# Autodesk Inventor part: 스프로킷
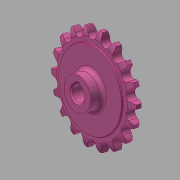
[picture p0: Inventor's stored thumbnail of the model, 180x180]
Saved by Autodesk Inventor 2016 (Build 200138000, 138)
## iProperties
Created: 2016-03
Part Number: 스프로킷
Material: 강철, 탄소
Document SubType Name: Modeling
Designer: mduedu
Density: 7.87 g/cm^3
Mass: 301.818 g
Surface Area: 124.882 cm^2
Volume: 38.3505 cm^3
Appearance: 분홍색
Author: mduedu
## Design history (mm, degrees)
sketch "스케치1"
  geometry: L1 (0, 5)-(29.5, 5); L2 (29.5, 5)-(29.5, 4.1); L3 (30, 3.6)-(33.625, 3.6); L4 (40, 2)-(40, 0); L5 (40, 0)-(0, 0); L6 (0, 0)-(0, 5); L7 (0, -5)-(29.5, -5); L8 (29.5, -5)-(29.5, -4.1); L9 (30, -3.6)-(33.625, -3.6); L10 (40, -2)-(40, 0); L11 (0, 0)-(0, -5); A1 r 13.5 centre (33.625, -9.9) between (40, 2) and (33.625, 3.6); A2 r 13.5 centre (33.625, 9.9) between (33.625, -3.6) and (40, -2); A3 r 0.5 centre (30, 4.1) between (29.5, 4.1) and (30, 3.6); A4 r 0.5 centre (30, -4.1) between (30, -3.6) and (29.5, -4.1); 2 further points
  constraints: 22 end point, 8 point on circle, 6 symmetric about line, 5 tangent, 4 centre point, 4 parallel, 4 point on line, 1 equal radius, 1 horizontal, 1 perpendicular, 1 other
  dimensions: "d0" = 80 diameter of L4 L6; "d2" = 59 diameter of L2 L6; "d3" = 1.6 vertical distance of L4.start L3.end; "d4" = 3.6 distance from line of L4.end L3; "d5" = 5 distance between parallel lines of L5 L1; "d6" = 13.5 radius of A1; "d15" = 0.5 radius of A3
revolve "회전1" sketch "스케치1" stored, may be unused: angle "d7" = 90 deg
sketch "스케치2" dims "d8" = 65.2, "d11" = 80
  geometry: L1 (0, 0)-(0, 32.6); A1 r 36.57 centre (0, 0) between (-16.231, 32.771) and (0, 36.57); A2 r 3.97 centre (0, 36.57) between (-3.866, 35.665) and (0, 32.6); A3 r 12.7 centre (-16.231, 32.771) between (-3.866, 35.665) and (-5.534, 39.615); A4 r 12.7 centre (16.231, 32.771) between (5.534, 39.615) and (3.866, 35.665); A5 r 3.97 centre (0, 36.57) between (0, 32.6) and (3.866, 35.665); A6 r 40 centre (0, 0) between (5.534, 39.615) and (-5.534, 39.615); 2 further points
  constraints: 12 point on circle, 6 centre point, 4 coincident, 3 symmetric about line, 2 end point, 1 point on line, 1 tangent, 1 vertical, 1 vertical alignment, 7 other
  dimensions: "d10" = 73.14 diameter of A1; "d12" = 12.7 radius of A3
extrude "돌출1" cut sketch "스케치2" stored distance "d13" = 10; taper "d14" = 0 deg
sketch "스케치3"
  geometry: C1 r 12.5 at (0, 0); 1 further point
  constraints: 1 centre point, 1 coincident
  dimensions: "d19" = 25 diameter of C1
extrude "돌출2" join sketch "스케치3" distance "d20" = 10; taper "d21" = 0 deg
fillet "모깎기1" dims "d22" = 3
sketch "스케치4"
  geometry: L1 (-2, 0)-(2, 0); L2 (2, 0)-(2, 7.8); L3 (2, 7.8)-(-2, 7.8); L4 (-2, 7.8)-(-2, 0); C1 r 6 at (0, 0); 2 further points
  constraints: 8 end point, 2 coincident, 2 parallel, 1 centre point, 1 horizontal, 1 midpoint, 1 perpendicular
  dimensions: "d23" = 12 diameter of C1; "d25" = 4 distance of L2.end L3.end; "d26" = 7.8 distance of L1.end L2.end
extrude "돌출3" cut sketch "스케치4" stored distance "d27" = 8; taper "d28" = 0 deg
chamfer "모따기2" distance "d42" = 1; stored, may be unused: second distance "d43" = 2, angle "d44" = 45 deg
node "솔리드1"
pattern_circular "원형 패턴1" dims angle "d17" = 360 deg
